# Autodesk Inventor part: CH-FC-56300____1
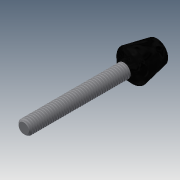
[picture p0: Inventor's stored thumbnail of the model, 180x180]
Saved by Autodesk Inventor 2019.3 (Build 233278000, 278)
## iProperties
Created: 2012-09
Part Number: CH-FC-56300____1
Material: Ogólny
Document SubType Name: Modeling
Designer: CADENGINEERING4
Density: 1 g/cm^3
Appearance: Domyślna
Author: CADENGINEERING4
Revision Number: ÈÎºÎ
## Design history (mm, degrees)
feature "NONE"
node "Bryła1"
